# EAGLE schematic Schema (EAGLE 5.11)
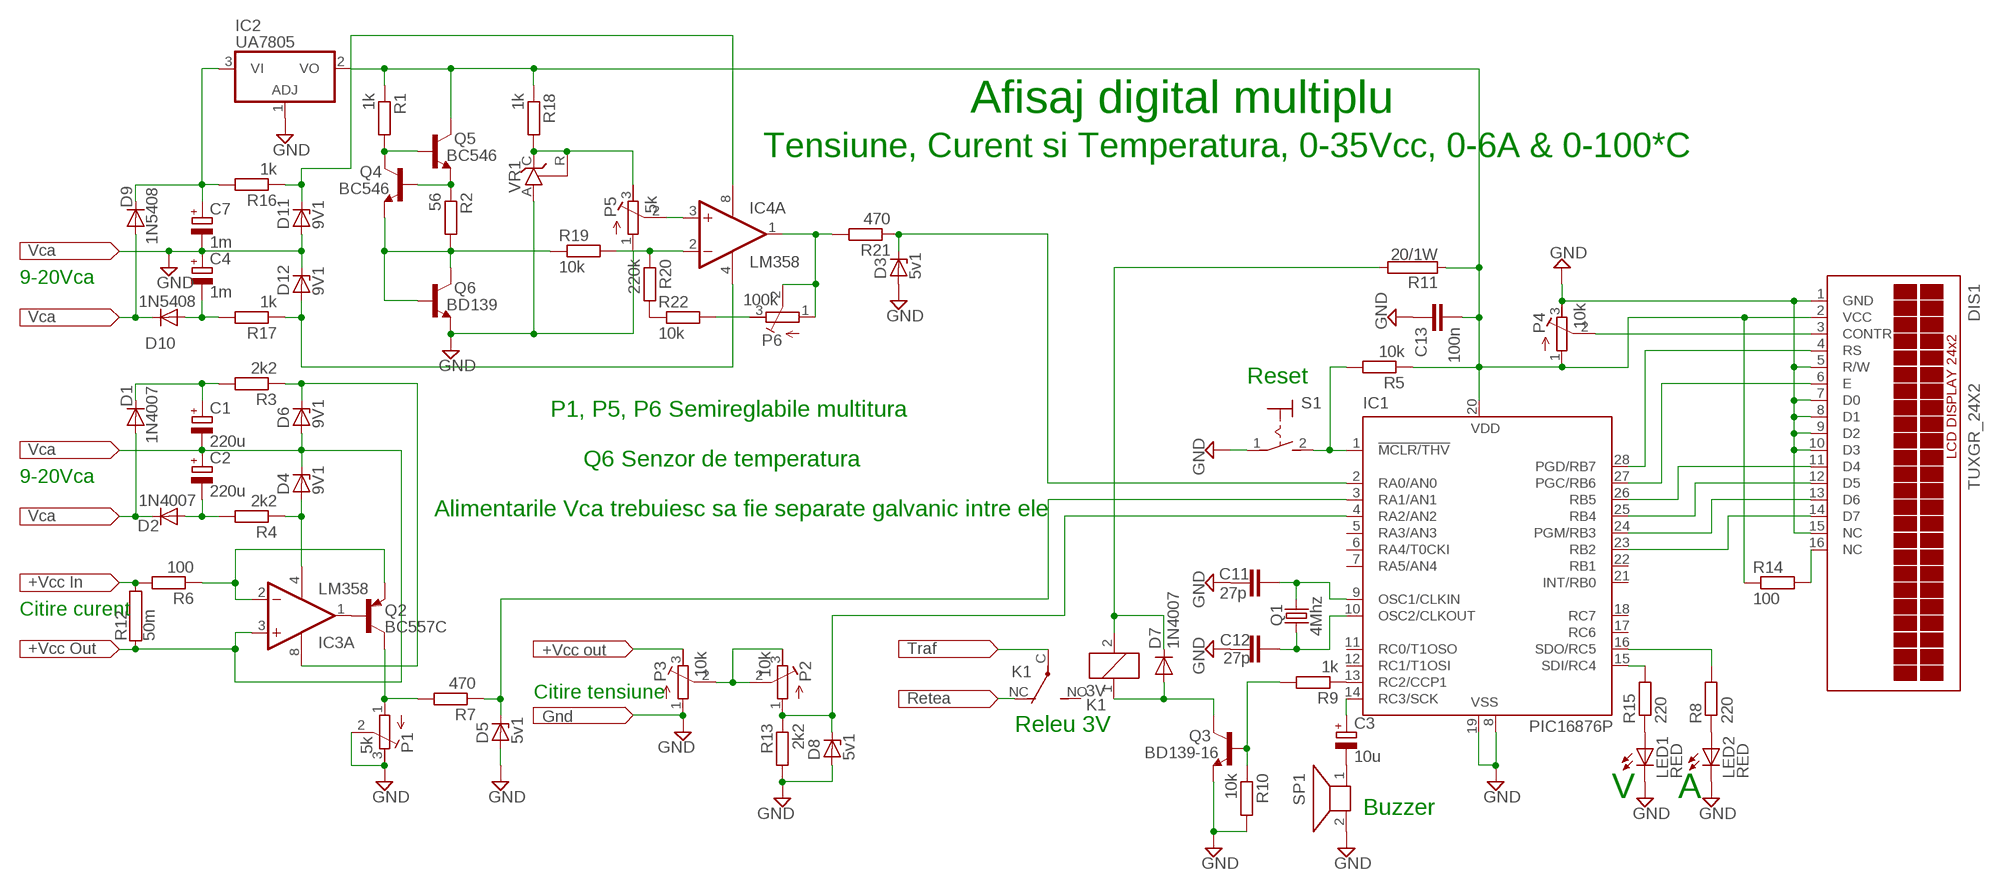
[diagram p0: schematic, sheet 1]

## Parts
C1  220u  CPOL-EU140CLH-0810  [140CLH-0810]
C2  220u  CPOL-EU140CLH-0810  [140CLH-0810]
C3  10u  CPOL-EU140CLH-0810  [140CLH-0810]
C4  1m  CPOL-EU140CLH-0810  [140CLH-0810]
C7  1m  CPOL-EU140CLH-0810  [140CLH-0810]
C11  27p  C-EU050-024X044  [C050-024X044]
C12  27p  C-EU050-024X044  [C050-024X044]
C13  100n  C-EU050-024X044  [C050-024X044]
D1  1N4007  1N4004  [DO41-10]
D2  1N4007  1N4004  [DO41-10]
D3  5v1  1N4728  [DO41Z10]
D4  9V1  1N4728  [DO41Z10]
D5  5v1  1N4728  [DO41Z10]
D6  9V1  1N4728  [DO41Z10]
D7  1N4007  1N4004  [DO41-10]
D8  5v1  1N4728  [DO41Z10]
D9  1N5408  1N4004  [DO41-10]
D10  1N5408  1N4004  [DO41-10]
D11  9V1  1N4728  [DO41Z10]
D12  9V1  1N4728  [DO41Z10]
DIS1  TUXGR_24X2  [TUXGR_24X2]
IC1  PIC16876P  [DIL28-3]
IC2  UA7805  317T  [TO220H]
IC3  LM358  AD8682R  [SO08]
IC4  LM358  AD8682R  [SO08]
K1  3V  CQ1-12V  [CQ1]
LED1  RED  LED3MM  [LED3MM]
LED2  RED  LED3MM  [LED3MM]
P1  5k  R-TRIMM64W  [RTRIM64W]
P2  10k  R-TRIMM64W  [RTRIM64W]
P3  10k  R-TRIMM64W  [RTRIM64W]
P4  10k  R-TRIMM64W  [RTRIM64W]
P5  5k  R-TRIMM64W  [RTRIM64W]
P6  100k  R-TRIMM64W  [RTRIM64W]
Q1  4Mhz  CRYSTALHC18U-V  [HC18U-V]
Q2  BC557C  [TO92-EBC]
Q3  BD139-16  BC546A  [TO92-EBC]
Q4  BC546  BC546A  [TO92-EBC]
Q5  BC546  BC546A  [TO92-EBC]
Q6  BD139  BC546A  [TO92-EBC]
R1  1k  R-EU_0207/10  [0207/10]
R2  56  R-EU_0207/10  [0207/10]
R3  2k2  R-EU_0207/10  [0207/10]
R4  2k2  R-EU_0207/10  [0207/10]
R5  10k  R-EU_0207/10  [0207/10]
R6  100  R-EU_0207/10  [0207/10]
R7  470  R-EU_0207/10  [0207/10]
R8  220  R-EU_0207/10  [0207/10]
R9  1k  R-EU_0207/10  [0207/10]
R10  10k  R-EU_0207/10  [0207/10]
R11  20/1W  RAC01  [AC01]
R12  50m  RCA0001  [CA0001]
R13  2k2  R-EU_0207/10  [0207/10]
R14  100  R-EU_0207/10  [0207/10]
R15  220  R-EU_0207/10  [0207/10]
R16  1k  R-EU_0207/10  [0207/10]
R17  1k  R-EU_0207/10  [0207/10]
R18  1k  R-EU_0207/10  [0207/10]
R19  10k  R-EU_0207/10  [0207/10]
R20  220k  R-EU_0207/10  [0207/10]
R21  470  R-EU_0207/10  [0207/10]
R22  10k  R-EU_0207/10  [0207/10]
S1  MS243  [MS243]
SP1  AL60P  [AL60P]
VR1  TL431CLP  [TO92-CLP]

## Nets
GND: C4.+ C7.- C11.1 C12.1 C13.1 D3.A D5.A D8.A D11.A D12.C DIS1.1(GND) DIS1.5(R/W) DIS1.7(D0) DIS1.8(D1) DIS1.9(D2) DIS1.10(D3) DIS1.15(NC) IC1.8(VSS) IC1.19(VSS) IC2.1(ADJ) LED1.K(C) LED2.K(C) P1.2(S) P1.3(A) P3.1(E) P4.3(A) P5.1(E) Q3.E Q6.E R10.2 R13.2 S1.1(P) SP1.2 VR1.A
N$1: Q4.C Q5.B R1.2
N$2: C13.2 DIS1.2(VCC) IC1.20(VDD) IC2.2(VO) P4.1(E) Q5.C R1.1 R5.1 R11.1 R14.1 R18.1
N$3: DIS1.4(RS) IC1.28(PGD/RB7)
N$4: Q4.B Q5.E R2.1
N$5: Q4.E Q6.B Q6.C R2.2 R19.1
N$6: DIS1.6(E) IC1.27(PGC/RB6)
N$7: IC1.1(!MCLR/THV) R5.2 S1.2(S)
N$8: D1.A D2.C
N$9: C1.- C2.+ D4.C D6.A IC3.3(A:+IN) R12.1
N$10: C2.- D2.A R4.2
N$11: C1.+ D1.C R3.2
N$12: D6.C IC3.8(P:V+) R3.1
N$13: D5.C IC1.3(RA1/AN1) R7.1
N$14: IC3.1(A:OUT) Q2.B
N$15: D4.A IC3.4(P:V-) R4.1
N$16: R6.2 R12.2
N$17: IC3.2(A:-IN) Q2.E R6.1
N$18: DIS1.11(D4) IC1.26(RB5)
N$19: DIS1.3(CONTR) P4.2(S)
N$20: P2.2(S) P2.3(A) P3.2(S)
N$21: D9.A D10.C
N$22: P3.3(A)
N$23: C12.2 IC1.10(OSC2/CLKOUT) Q1.1
N$24: C11.2 IC1.9(OSC1/CLKIN) Q1.2
N$25: R20.2 R22.1
N$26: DIS1.12(D5) IC1.25(RB4)
N$27: DIS1.13(D6) IC1.24(PGM/RB3)
N$28: DIS1.14(D7) IC1.23(RB2)
N$29: DIS1.16(NC) R14.2
N$30: LED1.A R15.1
N$31: LED2.A R8.1
N$32: IC1.16(SDO/RC5) R8.2
N$33: P5.3(A) R18.2 VR1.C VR1.R
N$34: IC1.15(SDI/RC4) R15.2
N$35: C3.- SP1.1
N$36: C3.+ IC1.14(RC3/SCK)
N$37: P1.1(E) Q2.C R7.2
N$38: IC1.13(RC2/CCP1) R9.1
N$39: Q3.B R9.2 R10.1
N$40: D7.A K1.1 Q3.C
N$41: D7.C K1.2 R11.2
N$42: K1.NC(2:O)
N$43: K1.C(2:P)
N$44: C4.- D10.A R17.2
N$45: D8.C IC1.4(RA2/AN2) P2.1(E) R13.1
N$46: C7.+ D9.C IC2.3(VI) R16.2
N$47: P6.3(A) R22.2
N$48: D12.A IC4.4(P:V-) R17.1
N$49: D11.C IC4.8(P:V+) R16.1
N$50: IC4.1(A:OUT) P6.1(E) P6.2(S) R21.2
N$51: D3.C IC1.2(RA0/AN0) R21.1
N$53: IC4.3(A:+IN) P5.2(S)
N$54: IC4.2(A:-IN) R19.2 R20.1
Unconnected: IC1.5(RA3/AN3) IC1.6(RA4/T0CKI) IC1.7(RA5/AN4) IC1.11(RC0/T1OSO) IC1.12(RC1/T1OSI) IC1.17(RC6) IC1.18(RC7) IC1.21(INT/RB0) IC1.22(RB1) IC3.5(B:+IN) IC3.6(B:-IN) IC3.7(B:OUT) IC4.5(B:+IN) IC4.6(B:-IN) IC4.7(B:OUT) K1.NO(2:S)

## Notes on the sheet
- Afisaj digital multiplu
- Tensiune, Curent si Temperatura, 0-35Vcc, 0-6A & 0-100*C
- 9-20Vca
- Reset
- P1, P5, P6 Semireglabile multitura
- Q6 Senzor de temperatura
- 9-20Vca
- Alimentarile Vca trebuiesc sa fie separate galvanic intre ele
- Citire curent
- Citire tensiune
- Releu 3V
- V | A
- Buzzer

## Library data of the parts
C1-C4 C7 = resistor:CPOL-EU: POLARIZED CAPACITOR, European symbol
C11-C13 = resistor:C-EU: CAPACITOR, European symbol
D1 D2 D7 D9 D10 = diode:1N4004: DIODE
D3-D6 D8 D11 D12 = diode:1N4728: Z DIODE
DIS1 = display-lcd2:TUXGR_24X2: Tuxgraphics LCD display 20x2 characters reflective, without background light Source: tuxgr_20x2.pdf; OC_FARNELL: unknown; OC_NEWARK: unknown
IC1 = microchip:PIC16*876: MICROCONTROLLER flash type; OC_FARNELL: unknown; OC_NEWARK: unknown
IC2 = linear:*317: Positive VOLTAGE REGULATOR
IC3 IC4 = linear:AD8682: Dual Low Power, High Speed JFET Operational Amplifiers Source: http://www.analog.com/UploadedFiles/Data_Sheets/AD8682_8684.pdf
K1 = relay:CQ1-12V: AUTOMOTIVE QUIET RELAY NAiS Source: http://www.mew-europe.com/.. en_ds_61208_0000.pdf; OC_FARNELL: unknown; OC_NEWARK: unknown
LED1 LED2 = led:LED: LED
P1-P6 = resistor:R-TRIMM: Trimm resistor
Q1 = crystal:CRYSTAL: CRYSTAL; OC_FARNELL: unknown; OC_NEWARK: unknown
Q2 = transistor-pnp:BC557*: PNP Transistror
Q3-Q6 = transistor-npn:BC546*: NPN Transistor
R1-R10 R13-R22 = resistor:R-EU_: RESISTOR, European symbol
R11 R12 = resistor-power:R: Power Resitor; OC_FARNELL: unknown; OC_NEWARK: unknown
S1 = switch:MS243: TOGGLE SWITCH
SP1 = buzzer:AL60P: SPEAKER; OC_FARNELL: unknown; OC_NEWARK: unknown
VR1 = v-reg:TL431CLP: VOLTAGE REGULATOR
